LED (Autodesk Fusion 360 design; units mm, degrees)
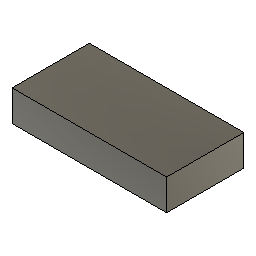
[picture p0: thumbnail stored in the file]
parameter "Hight_Z" = 0.2 (= "0.2 mm * Ratio")
sketch "Sketch1" plane through (0, 0, 0) normal (0, 0, 1) x axis (1, 0, 0)
  line L1 (-1, 0) -> (0, 0)
  line L2 (-1, 0.5) -> (-1, 0)
  line L3 (0, 0.5) -> (-1, 0.5)
  line L4 (0, 0) -> (0, 0.5)
  point P1 (0, 0)
  point P2 (0, 0)
  point P3 (-1, 0)
  point P5 (0, 0.5)
  horizontal L1
  vertical L2
  horizontal L3
  vertical L4
  coincident P1 P2
  dimension "d2" distance P2 P3 = 1 (= "( 1 * Ratio ) * 1 mm")
  dimension "d3" distance P2 P5 = 0.5 (= "( 0.5 * Ratio ) * 1 mm")
extrude "Extrude1" new body sketch "Sketch1" along normal blind 0.2 (= "Hight_Z")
